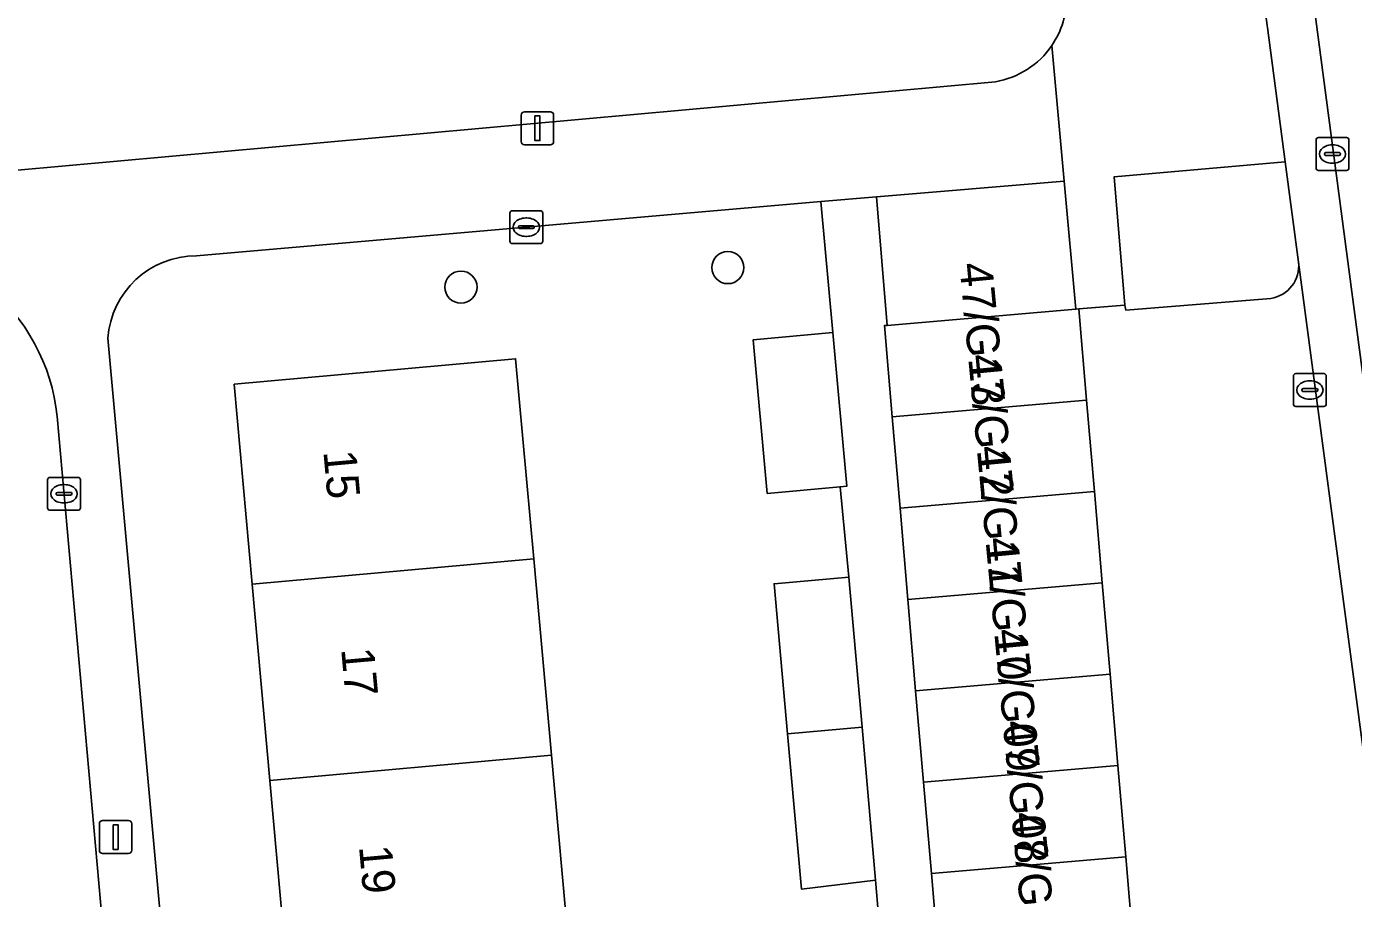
# Model space of a CAD drawing. Extents: x 160554 to 161248, y 385329 to 386506.
# Drawn here: x 161093.62 to 161134.07, y 385547.3 to 385573.86 of the extents above; entities that cross this region are included whole.
import ezdxf

# ---------------------------------------------------------------- set-up
doc = ezdxf.new("R2010")
doc.units = 0
for name, color, linetype in [('IMGEO_Boom', 7, 'Continuous'), ('IMGEO_Erf', 7, 'Continuous'), ('IMGEO_Groenvoorziening', 7, 'Continuous'), ('IMGEO_Kolk', 7, 'Continuous'), ('IMGEO_Lichtmast', 7, 'Continuous'), ('IMGEO_Pand', 7, 'Continuous'), ('IMGEO_Pand_nummerreeks', 7, 'Continuous'), ('IMGEO_Parkeervlak_open', 7, 'Continuous'), ('IMGEO_Rijbaan_lokaal_gesloten', 7, 'Continuous'), ('IMGEO_Rijbaan_lokaal_open', 7, 'Continuous'), ('IMGEO_Rioolput', 7, 'Continuous'), ('IMGEO_Voetpad_open', 7, 'Continuous')]:
    doc.layers.add(name, color=color, linetype=linetype)

msp = doc.modelspace()

# ---------------------------------------------------------------- linework, layer by layer
at = {"layer": 'IMGEO_Boom'}
for centre in [(161114.995, 385566.516), (161106.86, 385565.923)]:
    msp.add_circle(centre, 0.489, dxfattribs=at)
at = {"layer": 'IMGEO_Erf'}
for points in [[(161080.619, 385568.341), (161123.151, 385572.178)], [(161119.499, 385547.855), (161117.238, 385547.582), (161116.814, 385552.313), (161116.405, 385556.883), (161118.683, 385557.084), (161118.419, 385559.837), (161116.197, 385559.634), (161115.77, 385564.316), (161118.194, 385564.537), (161117.833, 385568.528), (161098.796, 385566.874)], [(161096.096, 385564.364), (161099.576, 385526.035)], [(161102.391, 385523.95), (161121.73, 385525.612), (161121.438, 385528.456), (161118.897, 385528.212), (161118.427, 385533.11), (161120.968, 385533.354), (161120.745, 385535.867), (161118.256, 385535.713), (161117.861, 385540.356), (161117.474, 385544.913), (161119.733, 385545.125), (161119.499, 385547.855)]]:
    msp.add_lwpolyline(points, dxfattribs=at)
msp.add_lwpolyline([(161110.154, 385545.687), (161113.05, 385545.948), (161113.59, 385539.971), (161110.693, 385539.71), (161111.232, 385533.733), (161111.782, 385527.636), (161103.204, 385526.863), (161102.654, 385532.959), (161102.115, 385538.936), (161101.577, 385544.913), (161101.038, 385550.89), (161100.499, 385556.867), (161099.949, 385562.964), (161108.527, 385563.737), (161109.077, 385557.641), (161109.616, 385551.664)], close=True, dxfattribs=at)
for centre, radius, start, end in [((161122.707, 385574.757), 2.619, 325.7495, 0.7405), ((161122.713, 385574.753), 2.612, 279.659, 325.7475), ((161098.792, 385564.171), 2.703, 89.9158, 175.907)]:
    msp.add_arc(centre, radius, start, end, dxfattribs=at)
at = {"layer": 'IMGEO_Groenvoorziening'}
for points in [[(161131.983, 385569.741), (161126.77, 385569.281), (161127.094, 385565.373), (161127.124, 385565.222), (161131.543, 385565.578)], [(161132.394, 385566.679), (161131.983, 385569.741)]]:
    msp.add_lwpolyline(points, dxfattribs=at)
msp.add_lwpolyline([(161125.249, 385569.151), (161119.53, 385568.676), (161119.857, 385564.757), (161125.599, 385565.249)], close=True, dxfattribs=at)
msp.add_arc((161131.399, 385566.569), 1.001, 278.277, 6.3197, dxfattribs=at)
at = {"layer": 'IMGEO_Kolk'}
for p, q in [((161108.352, 385567.322), (161108.352, 385568.174)), ((161108.427, 385568.248), (161109.279, 385568.248)), ((161108.84, 385568.028), (161108.865, 385568.028)), ((161109.353, 385568.174), (161109.353, 385567.322)), ((161108.611, 385567.742), (161108.611, 385567.754)), ((161109.049, 385567.705), (161108.651, 385567.705)), ((161108.654, 385567.791), (161109.052, 385567.791)), ((161108.863, 385567.468), (161108.838, 385567.468)), ((161109.095, 385567.754), (161109.095, 385567.742)), ((161109.279, 385567.248), (161108.427, 385567.248)), ((161132.237, 385562.359), (161132.237, 385563.211)), ((161132.312, 385563.285), (161133.164, 385563.285)), ((161132.725, 385563.065), (161132.75, 385563.065)), ((161133.238, 385563.211), (161133.238, 385562.359)), ((161132.496, 385562.779), (161132.496, 385562.791)), ((161132.934, 385562.742), (161132.536, 385562.742)), ((161132.539, 385562.828), (161132.937, 385562.828)), ((161132.98, 385562.791), (161132.98, 385562.779)), ((161133.164, 385562.285), (161132.312, 385562.285)), ((161132.748, 385562.505), (161132.723, 385562.505)), ((161094.258, 385559.199), (161094.258, 385560.051)), ((161094.333, 385560.125), (161095.185, 385560.125)), ((161094.746, 385559.905), (161094.771, 385559.905)), ((161095.259, 385560.051), (161095.259, 385559.199)), ((161094.517, 385559.619), (161094.517, 385559.631)), ((161094.955, 385559.582), (161094.557, 385559.582)), ((161094.56, 385559.668), (161094.958, 385559.668)), ((161095.001, 385559.631), (161095.001, 385559.619)), ((161095.185, 385559.125), (161094.333, 385559.125)), ((161094.769, 385559.345), (161094.744, 385559.345))]:
    msp.add_line(p, q, dxfattribs=at)
for points in [[(161108.352, 385567.322), (161108.352, 385568.174)], [(161108.427, 385568.248), (161109.279, 385568.248)], [(161109.353, 385568.174), (161109.353, 385567.322)], [(161109.279, 385567.248), (161108.427, 385567.248)], [(161132.237, 385562.359), (161132.237, 385563.211)], [(161132.312, 385563.285), (161133.164, 385563.285)], [(161133.238, 385563.211), (161133.238, 385562.359)], [(161133.164, 385562.285), (161132.312, 385562.285)], [(161094.258, 385559.199), (161094.258, 385560.051)], [(161094.333, 385560.125), (161095.185, 385560.125)], [(161095.259, 385560.051), (161095.259, 385559.199)], [(161095.185, 385559.125), (161094.333, 385559.125)]]:
    msp.add_lwpolyline(points, dxfattribs=at)
for centre, radius, start, end in [((161108.429, 385568.172), 0.0765, 91.552, 178.448), ((161108.429, 385568.172), 0.0765, 91.552, 178.448), ((161109.277, 385568.172), 0.0765, 1.552, 88.448), ((161109.277, 385568.172), 0.0765, 1.552, 88.448), ((161108.651, 385567.751), 0.0403, 85.8775, 175.7526), ((161108.648, 385567.741), 0.0366, 178.938, 274.7102), ((161109.052, 385567.748), 0.043, 264.8664, 352.4533), ((161109.056, 385567.753), 0.0386, 1.7309, 96.639), ((161108.429, 385567.324), 0.0765, 181.552, 268.448), ((161108.429, 385567.324), 0.0765, 181.552, 268.448), ((161109.277, 385567.324), 0.0765, 271.552, 358.448), ((161109.277, 385567.324), 0.0765, 271.552, 358.448), ((161132.314, 385563.209), 0.0765, 91.552, 178.448), ((161132.314, 385563.209), 0.0765, 91.552, 178.448), ((161133.162, 385563.209), 0.0765, 1.552, 88.448), ((161133.162, 385563.209), 0.0765, 1.552, 88.448), ((161132.536, 385562.788), 0.0403, 85.8775, 175.7526), ((161132.533, 385562.778), 0.0366, 178.938, 274.7102), ((161132.937, 385562.785), 0.043, 264.8664, 352.4533), ((161132.941, 385562.79), 0.0386, 1.7309, 96.639), ((161132.314, 385562.361), 0.0765, 181.552, 268.448), ((161132.314, 385562.361), 0.0765, 181.552, 268.448), ((161133.162, 385562.361), 0.0765, 271.552, 358.448), ((161133.162, 385562.361), 0.0765, 271.552, 358.448), ((161094.335, 385560.049), 0.0765, 91.552, 178.448), ((161094.335, 385560.049), 0.0765, 91.552, 178.448), ((161095.183, 385560.049), 0.0765, 1.552, 88.448), ((161095.183, 385560.049), 0.0765, 1.552, 88.448), ((161094.557, 385559.628), 0.0403, 85.8775, 175.7526), ((161094.554, 385559.618), 0.0366, 178.938, 274.7102), ((161094.958, 385559.625), 0.043, 264.8664, 352.4533), ((161094.962, 385559.63), 0.0386, 1.7309, 96.639), ((161094.335, 385559.201), 0.0765, 181.552, 268.448), ((161094.335, 385559.201), 0.0765, 181.552, 268.448), ((161095.183, 385559.201), 0.0765, 271.552, 358.448), ((161095.183, 385559.201), 0.0765, 271.552, 358.448)]:
    msp.add_arc(centre, radius, start, end, dxfattribs=at)
for centre, major_axis, ratio, start_param, end_param in [((161108.839, 385567.748), (-0.387, 0.002), 0.722429, 4.712389, 7.853982), ((161108.864, 385567.748), (-0.39, 0.002), 0.717154, 1.570796, 4.712389), ((161132.724, 385562.785), (-0.387, 0.002), 0.722429, 4.712389, 7.853982), ((161132.749, 385562.785), (-0.39, 0.002), 0.717154, 1.570796, 4.712389), ((161094.745, 385559.625), (-0.387, 0.002), 0.722429, 4.712389, 7.853982), ((161094.77, 385559.625), (-0.39, 0.002), 0.717154, 1.570796, 4.712389)]:
    msp.add_ellipse(centre, major_axis=major_axis, ratio=ratio, start_param=start_param, end_param=end_param, dxfattribs=at)
at = {"layer": 'IMGEO_Lichtmast'}
for p, q in [((161108.695, 385570.361), (161108.695, 385571.161)), ((161108.695, 385571.161), (161108.695, 385570.361)), ((161108.795, 385571.261), (161109.585, 385571.261)), ((161109.585, 385571.261), (161108.795, 385571.261)), ((161109.685, 385571.161), (161109.685, 385570.361)), ((161109.685, 385570.361), (161109.685, 385571.161)), ((161109.585, 385570.261), (161108.795, 385570.261)), ((161108.795, 385570.261), (161109.585, 385570.261)), ((161095.837, 385548.767), (161095.837, 385549.567)), ((161095.837, 385549.567), (161095.837, 385548.767)), ((161095.937, 385549.667), (161096.727, 385549.667)), ((161096.727, 385549.667), (161095.937, 385549.667)), ((161096.827, 385549.567), (161096.827, 385548.767)), ((161096.827, 385548.767), (161096.827, 385549.567)), ((161096.727, 385548.667), (161095.937, 385548.667)), ((161095.937, 385548.667), (161096.727, 385548.667))]:
    msp.add_line(p, q, dxfattribs=at)
for points in [[(161109.115, 385571.136), (161109.265, 385571.136), (161109.265, 385570.386), (161109.115, 385570.386), (161109.115, 385571.136)], [(161096.257, 385549.542), (161096.407, 385549.542), (161096.407, 385548.792), (161096.257, 385548.792), (161096.257, 385549.542)]]:
    msp.add_lwpolyline(points, dxfattribs=at)
for centre, start, end in [((161108.795, 385571.161), 90, 180), ((161108.795, 385571.161), 90, 180), ((161109.585, 385571.161), 0, 90), ((161109.585, 385571.161), 360, 90), ((161108.795, 385570.361), 180, 270), ((161108.795, 385570.361), 180, 270), ((161109.585, 385570.361), 270, 0), ((161109.585, 385570.361), 270, 0), ((161095.937, 385549.567), 90, 180), ((161095.937, 385549.567), 90, 180), ((161096.727, 385549.567), 0, 90), ((161096.727, 385549.567), 360, 90), ((161095.937, 385548.767), 180, 270), ((161095.937, 385548.767), 180, 270), ((161096.727, 385548.767), 270, 0), ((161096.727, 385548.767), 270, 0)]:
    msp.add_arc(centre, 0.1, start, end, dxfattribs=at)
at = {"layer": 'IMGEO_Pand'}
for points in [[(161125.69, 385565.257), (161125.599, 385565.249), (161119.857, 385564.757), (161119.766, 385564.749), (161120.005, 385561.966), (161125.929, 385562.475)], [(161118.194, 385564.537), (161115.77, 385564.316), (161116.197, 385559.634), (161118.419, 385559.837), (161118.621, 385559.855)], [(161109.077, 385557.641), (161108.527, 385563.737), (161099.949, 385562.964), (161100.499, 385556.867)], [(161125.929, 385562.475), (161120.005, 385561.966), (161120.244, 385559.185), (161126.168, 385559.693)], [(161126.168, 385559.693), (161120.244, 385559.185), (161120.483, 385556.403), (161126.407, 385556.912)], [(161100.499, 385556.867), (161101.038, 385550.89), (161109.616, 385551.664), (161109.077, 385557.641)], [(161118.683, 385557.084), (161116.405, 385556.883), (161116.814, 385552.313), (161119.087, 385552.518)], [(161126.407, 385556.912), (161120.483, 385556.403), (161120.721, 385553.621), (161126.646, 385554.13)], [(161126.646, 385554.13), (161120.721, 385553.621), (161120.96, 385550.839), (161126.885, 385551.348)], [(161119.087, 385552.518), (161116.814, 385552.313), (161117.238, 385547.582), (161119.499, 385547.855)], [(161110.154, 385545.687), (161109.616, 385551.664), (161101.038, 385550.89), (161101.577, 385544.913)], [(161126.885, 385551.348), (161120.96, 385550.839), (161121.199, 385548.058), (161127.124, 385548.566)], [(161127.124, 385548.566), (161121.199, 385548.058), (161121.438, 385545.276), (161127.362, 385545.785)]]:
    msp.add_lwpolyline(points, close=True, dxfattribs=at)
at = {"layer": 'IMGEO_Parkeervlak_open'}
for points in [[(161137.405, 385528.949), (161136.719, 385534.065), (161132.394, 385566.679)], [(161131.543, 385565.578), (161127.124, 385565.222), (161127.094, 385565.373), (161125.69, 385565.257), (161125.929, 385562.475), (161126.168, 385559.693), (161126.407, 385556.912), (161126.646, 385554.13), (161126.885, 385551.348), (161127.124, 385548.566), (161127.362, 385545.785), (161127.601, 385543.003), (161127.84, 385540.221), (161128.079, 385537.439), (161128.318, 385534.658), (161128.557, 385531.876), (161128.796, 385529.094), (161130.319, 385529.237), (161135.137, 385529.71), (161136.341, 385529.83)]]:
    msp.add_lwpolyline(points, dxfattribs=at)
msp.add_arc((161131.399, 385566.569), 1.001, 278.277, 6.3197, dxfattribs=at)
at = {"layer": 'IMGEO_Rijbaan_lokaal_gesloten'}
msp.add_lwpolyline([(161129.001, 385603.744), (161126.296, 385624.071), (161124.809, 385623.89), (161124.823, 385623.758), (161127.335, 385604.916), (161131.436, 385573.892), (161131.444, 385573.829), (161131.983, 385569.741), (161132.394, 385566.679), (161136.719, 385534.065), (161137.405, 385528.949), (161137.609, 385527.41), (161138.381, 385521.493), (161138.515, 385520.471), (161140.193, 385507.547), (161141.009, 385501.397), (161143.236, 385484.558), (161144.696, 385484.751), (161142.364, 385502.586), (161138.335, 385533.123)], close=True, dxfattribs=at)
at = {"layer": 'IMGEO_Rijbaan_lokaal_open'}
msp.add_lwpolyline([(161140.522, 385535.764), (161128.787, 385624.365), (161126.296, 385624.071), (161129.001, 385603.744), (161138.335, 385533.123), (161142.364, 385502.586), (161144.696, 385484.751), (161147.193, 385485.072)], close=True, dxfattribs=at)
msp.add_lwpolyline([(161097.451, 385529.564), (161094.547, 385561.983)], dxfattribs=at)
msp.add_arc((161088.706, 385561.398), 5.87, 5.7201, 96.9389, dxfattribs=at)
at = {"layer": 'IMGEO_Rioolput'}
for p, q in [((161132.927, 385569.551), (161132.927, 385570.403)), ((161133.002, 385570.477), (161133.854, 385570.477)), ((161133.928, 385570.403), (161133.928, 385569.551)), ((161133.186, 385569.971), (161133.186, 385569.983)), ((161133.624, 385569.934), (161133.226, 385569.934)), ((161133.229, 385570.02), (161133.627, 385570.02)), ((161133.415, 385570.257), (161133.44, 385570.257)), ((161133.67, 385569.983), (161133.67, 385569.971)), ((161133.438, 385569.697), (161133.413, 385569.697)), ((161133.854, 385569.477), (161133.002, 385569.477))]:
    msp.add_line(p, q, dxfattribs=at)
for points in [[(161132.927, 385569.551), (161132.927, 385570.403)], [(161133.002, 385570.477), (161133.854, 385570.477)], [(161133.928, 385570.403), (161133.928, 385569.551)], [(161133.854, 385569.477), (161133.002, 385569.477)]]:
    msp.add_lwpolyline(points, dxfattribs=at)
for centre, radius, start, end in [((161133.004, 385570.401), 0.0765, 91.552, 178.448), ((161133.004, 385570.401), 0.0765, 91.552, 178.448), ((161133.852, 385570.401), 0.0765, 1.552, 88.448), ((161133.852, 385570.401), 0.0765, 1.552, 88.448), ((161133.226, 385569.98), 0.0403, 85.8775, 175.7526), ((161133.223, 385569.97), 0.0366, 178.938, 274.7102), ((161133.627, 385569.977), 0.043, 264.8664, 352.4533), ((161133.631, 385569.982), 0.0386, 1.7309, 96.639), ((161133.004, 385569.553), 0.0765, 181.552, 268.448), ((161133.004, 385569.553), 0.0765, 181.552, 268.448), ((161133.852, 385569.553), 0.0765, 271.552, 358.448), ((161133.852, 385569.553), 0.0765, 271.552, 358.448)]:
    msp.add_arc(centre, radius, start, end, dxfattribs=at)
for centre, major_axis, ratio, start_param, end_param in [((161133.414, 385569.977), (-0.387, 0.002), 0.722429, 4.712389, 7.853982), ((161133.439, 385569.977), (-0.39, 0.002), 0.717154, 1.570796, 4.712389)]:
    msp.add_ellipse(centre, major_axis=major_axis, ratio=ratio, start_param=start_param, end_param=end_param, dxfattribs=at)
at = {"layer": 'IMGEO_Voetpad_open'}
for points in [[(161124.872, 385573.283), (161125.249, 385569.151), (161125.599, 385565.249), (161125.69, 385565.257), (161127.094, 385565.373), (161126.77, 385569.281), (161131.983, 385569.741), (161131.444, 385573.829)], [(161131.444, 385573.829), (161131.436, 385573.892)], [(161098.796, 385566.874), (161117.833, 385568.528), (161119.53, 385568.676), (161125.249, 385569.151), (161124.872, 385573.283)], [(161123.151, 385572.178), (161080.619, 385568.341)], [(161121.438, 385545.276), (161121.199, 385548.058), (161120.96, 385550.839), (161120.721, 385553.621), (161120.483, 385556.403), (161120.244, 385559.185), (161120.005, 385561.966), (161119.766, 385564.749), (161119.857, 385564.757), (161119.53, 385568.676), (161117.833, 385568.528), (161118.194, 385564.537), (161118.621, 385559.855), (161118.419, 385559.837), (161118.683, 385557.084), (161119.087, 385552.518), (161119.499, 385547.855), (161119.733, 385545.125)], [(161099.576, 385526.035), (161096.096, 385564.364)], [(161094.547, 385561.983), (161097.451, 385529.564)]]:
    msp.add_lwpolyline(points, dxfattribs=at)
for centre, radius, start, end in [((161122.707, 385574.757), 2.619, 325.7495, 0.7405), ((161122.713, 385574.753), 2.612, 279.659, 325.7475), ((161088.706, 385561.398), 5.87, 5.7201, 96.9389), ((161098.792, 385564.171), 2.703, 89.9158, 175.907)]:
    msp.add_arc(centre, radius, start, end, dxfattribs=at)

# ---------------------------------------------------------------- texts
at = {"layer": 'IMGEO_Pand_nummerreeks'}
for s, rotation, p in [('47/G13', 275.4085, (161122.051, 385566.633)), ('47/G12', 275.4102, (161122.315, 385563.843)), ('47/G11', 275.4102, (161122.58, 385561.053)), ('15', 275.1521, (161102.665, 385560.914)), ('47/G10', 275.4102, (161122.844, 385558.264)), ('47/G09', 275.4102, (161123.108, 385555.475)), ('17', 275.1521, (161103.207, 385554.897)), ('47/G08', 275.4102, (161123.372, 385552.685)), ('47/G07', 275.4102, (161123.636, 385549.896)), ('19', 275.1521, (161103.75, 385548.88))]:
    msp.add_text(s, height=1, rotation=rotation, dxfattribs=at).set_placement(p)

doc.saveas('drawing.dxf')
